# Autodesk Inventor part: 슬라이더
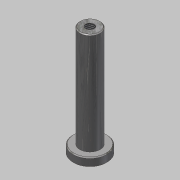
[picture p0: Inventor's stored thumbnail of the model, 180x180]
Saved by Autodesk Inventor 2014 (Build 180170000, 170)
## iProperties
Created: 2016-02
Part Number: 슬라이더
Material: 스테인리스강
Document SubType Name: Modeling
Designer: mduedu
Density: 8.08 g/cm^3
Mass: 65.4431 g
Surface Area: 33.4413 cm^2
Volume: 8.0994 cm^3
Appearance: 반광택
Author: mduedu
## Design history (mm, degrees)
sketch "스케치1"
  geometry: C1 r 10 at (0, 0); 1 further point
  constraints: 1 centre point, 1 coincident
  dimensions: "d0" = 20 diameter of C1
extrude "돌출1" new body sketch "스케치1" distance "d1" = 5; taper "d2" = 0 deg
sketch "스케치2"
  geometry: C1 r 6 at (0, 0); 1 further point
  constraints: 1 centre point, 1 coincident
  dimensions: "d3" = 12 diameter of C1
extrude "돌출2" join sketch "스케치2" distance "d4" = 60; taper "d5" = 0 deg
chamfer "모따기1" distance "d6" = 0.5; stored, may be unused: second distance "d7" = 2, angle "d8" = 45 deg
hole "구멍1" diameter "d11" = 4.917; stored, may be unused: countersink angle "d15" = 90 deg, drill point angle "d17" = 118 deg; dims "d9" = 10, "d10" = 10, "d12" = 10, "d13" = 4, "d14" = 2, "d16" = 12
chamfer "모따기2" distance "d18" = 0.5; stored, may be unused: second distance "d19" = 2, angle "d20" = 45 deg
node "솔리드1"
